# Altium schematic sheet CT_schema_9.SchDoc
size 209 x 185 mm
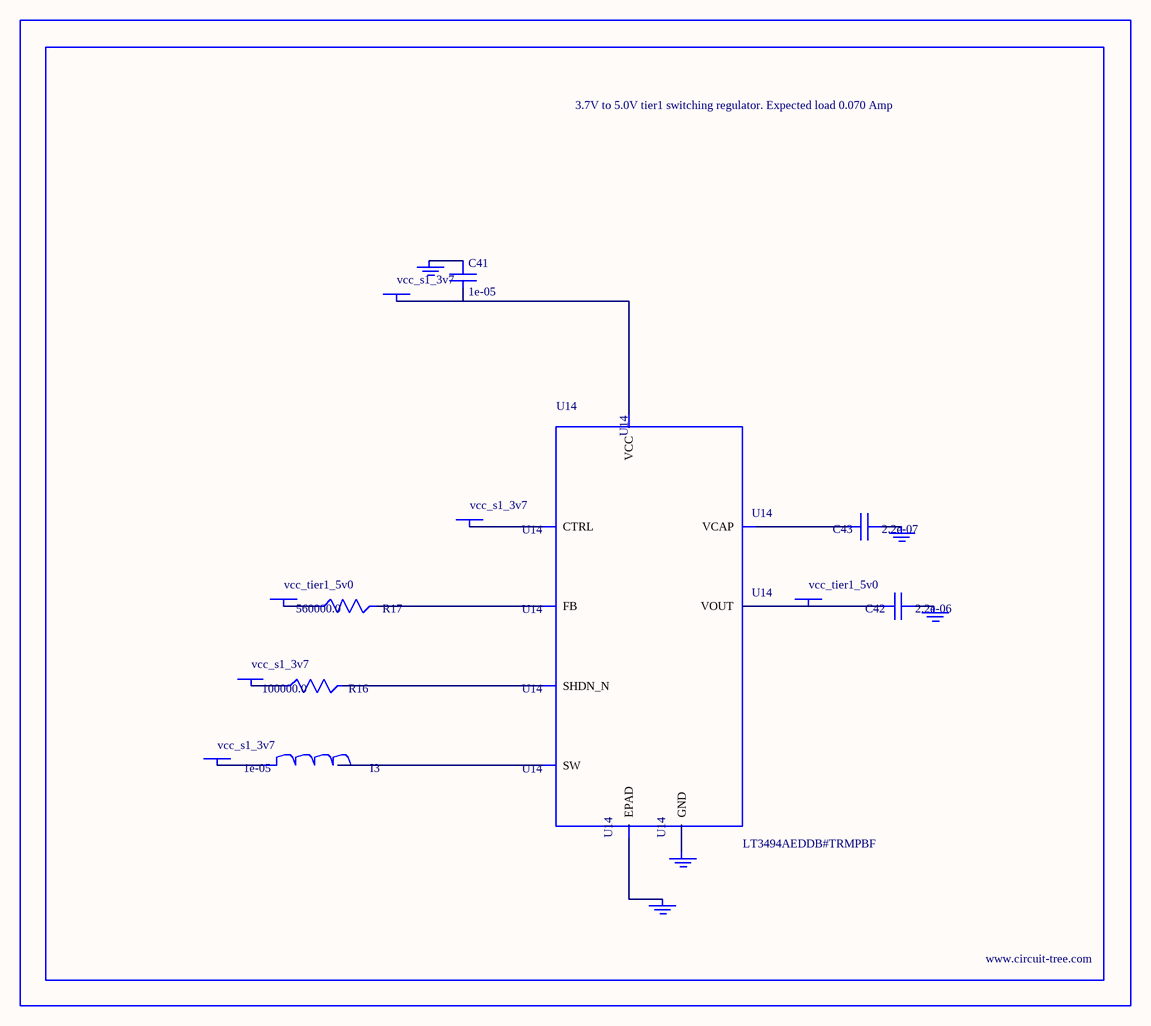
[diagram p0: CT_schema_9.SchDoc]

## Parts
BORDER8  (no value)
C41  1e-05  [C1210]
C42  2.2e-06  [C0603]
C43  2.2e-07  [C0603]
GND_INSTANCE_8_0  (no value)
GND_INSTANCE_8_1  (no value)
GND_INSTANCE_8_2  (no value)
GND_INSTANCE_8_3  (no value)
GND_INSTANCE_8_4  (no value)
I3  1e-05  [L1210]
POWER_INSTANCE_8_0  vcc_s1_3v7
POWER_INSTANCE_8_1  vcc_s1_3v7
POWER_INSTANCE_8_2  vcc_s1_3v7
POWER_INSTANCE_8_3  vcc_s1_3v7
POWER_INSTANCE_8_4  vcc_tier1_5v0
POWER_INSTANCE_8_5  vcc_tier1_5v0
R16  100000.0  [R0603]
R17  560000.0  [R0603]
U14  LT3494AEDDB#TRMPBF  [DFN-8_DDB]

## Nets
NetC41_1: C41.1 GND_INSTANCE_8_0.0(GND)
NetC41_2: C41.2 POWER_INSTANCE_8_1.0(PWR) U14.3(VCC)
NetC42_1: C42.1 GND_INSTANCE_8_1.0(GND)
NetC42_2: C42.2 POWER_INSTANCE_8_5.0(PWR) U14.7(VOUT)
NetC43_1: C43.1 GND_INSTANCE_8_2.0(GND)
NetC43_2: C43.2 U14.8(VCAP)
NetGND_INSTANCE_8_3_0: GND_INSTANCE_8_3.0(GND) U14.9(EPAD)
NetGND_INSTANCE_8_4_0: GND_INSTANCE_8_4.0(GND) U14.2(GND)
NetI3_1: I3.1 POWER_INSTANCE_8_0.0(PWR)
NetI3_2: I3.2 U14.1(SW)
NetPOWER_INSTANCE_8_2_0: POWER_INSTANCE_8_2.0(PWR) U14.4(CTRL)
NetPOWER_INSTANCE_8_3_0: POWER_INSTANCE_8_3.0(PWR) R16.1
NetPOWER_INSTANCE_8_4_0: POWER_INSTANCE_8_4.0(PWR) R17.1
NetR16_2: R16.2 U14.5(SHDN_N)
NetR17_2: R17.2 U14.6(FB)

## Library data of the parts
BORDER8 = BORDER_PAGE8
C41 = C1210C106K5PACTU
C42 = GRM188R61H225KE1115D
C43 = C0603C224K3RAC
GND_INSTANCE_8_0-GND_INSTANCE_8_4 = GND
I3 = CBC3225T100MR
POWER_INSTANCE_8_0-POWER_INSTANCE_8_5 = PWR
R16 = RC0603JR-07100KL
R17 = RC0603JR-07560KL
